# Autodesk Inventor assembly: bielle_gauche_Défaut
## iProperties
Shininess: 64.0
Length Units: 11269
Angle Units: 11279
Time Units: 11290
Mass Units: 11283
Length Display Precision: 3
Angle Display Precision: 2
Compacted: True
Created: 2006-01
Part Number: bielle_gauche_Défaut
Document SubType Name: Assembly
Designer: riri
Density: 0.0
Volumn: 0.0
Area: 0.0
PropertySet Name: Model Information
Control State: 0
Master: False
Checked Out: False
Author: riri
